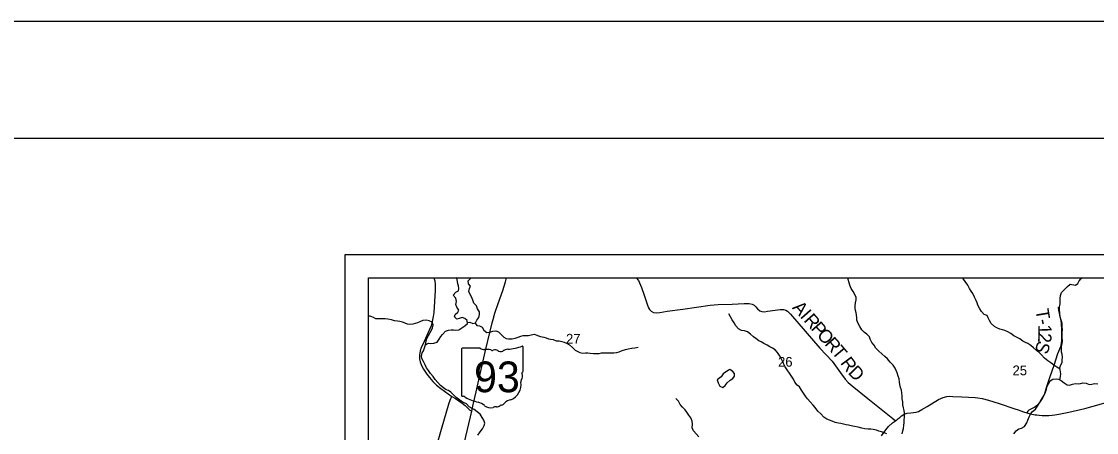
# Model space of a CAD drawing. Extents: x 0 to 34, y 0 to 22.
# Drawn here: x 22.027 to 26.642, y 20.236 to 22 of the extents above; entities that cross this region are included whole.
import ezdxf

# ---------------------------------------------------------------- set-up
doc = ezdxf.new("R2010")
doc.units = 0
for name, color, linetype in [('GM_X_County_Road', 7, 'Continuous'), ('GM_X_County_Road_Text', 7, 'Continuous'), ('GM_X_Major_River', 7, 'Continuous'), ('GM_X_Minor_Lake', 7, 'Continuous'), ('GM_X_Minor_River', 7, 'Continuous'), ('GM_X_Section_Text', 7, 'Continuous'), ('GM_X_State_Location', 7, 'Continuous'), ('GM_X_State_Route', 7, 'Continuous'), ('GM_X_State_Shield', 7, 'Continuous'), ('GM_X_Township_Road', 7, 'Continuous'), ('GM_X_Township_Road_Text', 7, 'Continuous'), ('SH_Border', 7, 'Continuous'), ('SH_Cut_Line', 7, 'Continuous'), ('SH_Data', 7, 'Continuous')]:
    doc.layers.add(name, color=color, linetype=linetype)

msp = doc.modelspace()

# ---------------------------------------------------------------- linework, layer by layer
at = {"layer": 'GM_X_County_Road'}
for points in [[(23.798, 20.9), (23.801, 20.8876), (23.8033, 20.872), (23.8024, 20.8451), (23.7967, 20.7508), (23.7941, 20.7333), (23.7905, 20.7124), (23.7852, 20.6946), (23.779, 20.6783), (23.761, 20.6397), (23.7502, 20.6144), (23.7428, 20.6005), (23.7389, 20.5865), (23.7362, 20.5679), (23.7355, 20.5527), (23.7392, 20.5389), (23.7442, 20.5239), (23.7532, 20.5078), (23.7677, 20.4871), (23.7794, 20.4722), (23.7932, 20.4549), (23.8091, 20.4388), (23.8273, 20.4248), (23.8749, 20.3912), (23.8901, 20.382), (23.9053, 20.3714), (23.9186, 20.3622), (23.9317, 20.3514), (23.9515, 20.3326), (23.96, 20.3273)], [(24.6657, 20.9), (24.6759, 20.8882), (24.689, 20.8583), (24.7005, 20.8261), (24.7148, 20.7822), (24.7189, 20.7716), (24.7228, 20.7647), (24.7309, 20.7566), (24.741, 20.7518), (24.752, 20.7502), (24.7677, 20.7513), (24.7997, 20.7564), (24.8661, 20.7656), (24.9837, 20.7826), (25.0177, 20.7856), (25.0787, 20.7868), (25.1298, 20.79), (25.1514, 20.79), (25.1634, 20.787), (25.1723, 20.7824), (25.1799, 20.7753), (25.1868, 20.7672), (25.1967, 20.7585), (25.2061, 20.7553), (25.2163, 20.7541), (25.2305, 20.7562), (25.2839, 20.764), (25.2988, 20.764), (25.3092, 20.7605), (25.3156, 20.7566), (25.3212, 20.7516), (25.3283, 20.7435), (25.3913, 20.6708), (25.4548, 20.5986), (25.507, 20.542), (25.5427, 20.4923), (25.5639, 20.4654), (25.5767, 20.4514), (25.594, 20.4364), (25.6612, 20.3824), (25.7679, 20.2959), (25.7793, 20.2864)], [(23.7323, 20.033), (23.737, 20.0391), (23.7498, 20.0501), (23.7703, 20.0665), (23.7745, 20.0748), (23.779, 20.0858), (23.7916, 20.1246), (23.8127, 20.1904), (23.833, 20.2612), (23.8405, 20.2846), (23.8637, 20.3631), (23.8706, 20.3822), (23.8749, 20.3912)]]:
    msp.add_lwpolyline(points, dxfattribs=at)
at = {"layer": 'GM_X_Major_River'}
msp.add_lwpolyline([(26.2869, 20.2302), (26.2968, 20.2438), (26.309, 20.2524), (26.3204, 20.2543), (26.3334, 20.2625), (26.3437, 20.2772), (26.348, 20.2886), (26.3534, 20.3029), (26.3588, 20.3143), (26.3676, 20.3256), (26.3802, 20.3369), (26.3893, 20.349), (26.3982, 20.3637), (26.4039, 20.3739), (26.4108, 20.3848), (26.417, 20.3962), (26.4235, 20.409), (26.4274, 20.4219), (26.4309, 20.4332), (26.437, 20.4453), (26.4428, 20.4574), (26.4546, 20.4653), (26.469, 20.4667), (26.4789, 20.4651), (26.4902, 20.4594), (26.503, 20.4498), (26.5163, 20.4413), (26.5265, 20.4397), (26.539, 20.4431), (26.552, 20.4464), (26.5648, 20.4455), (26.5743, 20.4466), (26.5842, 20.4488), (26.5979, 20.4479), (26.6107, 20.4422), (26.6217, 20.444), (26.6343, 20.4465), (26.6475, 20.4449)], dxfattribs=at)
at = {"layer": 'GM_X_Minor_Lake'}
for points in [[(25.0722, 20.5036), (25.0682, 20.5061), (25.0535, 20.4981), (25.0402, 20.4886), (25.0312, 20.4753), (25.0138, 20.4616)], [(25.0138, 20.4616), (25.0177, 20.4495), (25.0256, 20.4351), (25.0378, 20.4287), (25.0476, 20.4382), (25.0563, 20.4488), (25.0702, 20.4606), (25.0804, 20.4678), (25.0887, 20.4785), (25.0876, 20.4891), (25.08, 20.4989), (25.0722, 20.5036)]]:
    msp.add_lwpolyline(points, dxfattribs=at)
at = {"layer": 'GM_X_Minor_River'}
for points in [[(23.7619, 20.6128), (23.774, 20.6197), (23.7838, 20.6178), (23.7978, 20.619), (23.811, 20.6243), (23.8205, 20.6372), (23.8269, 20.6475), (23.8344, 20.6573), (23.848, 20.6706), (23.8601, 20.6748), (23.8722, 20.6768), (23.882, 20.6764), (23.8923, 20.6757), (23.904, 20.6772), (23.9172, 20.6848), (23.9304, 20.6944), (23.9414, 20.7046), (23.941, 20.7168), (23.9311, 20.7251), (23.9193, 20.7303), (23.9057, 20.7258), (23.8959, 20.7227), (23.8856, 20.7325), (23.8883, 20.7428), (23.9007, 20.7523), (23.9045, 20.7618), (23.8954, 20.7739), (23.8919, 20.7849), (23.8941, 20.7981), (23.8918, 20.8125), (23.8808, 20.8258), (23.8914, 20.838), (23.9031, 20.844), (23.9049, 20.8547), (23.9034, 20.8649), (23.9007, 20.8748), (23.8988, 20.8842), (23.8961, 20.8979), (23.8932, 20.9)], [(23.9413, 20.7079), (23.9516, 20.7103), (23.9649, 20.7035), (23.9762, 20.7062), (23.9822, 20.7187), (23.9909, 20.729), (23.9931, 20.7423), (23.9931, 20.754), (23.9855, 20.7665), (23.9798, 20.7798), (23.9695, 20.7908), (23.9649, 20.8036), (23.9584, 20.818), (23.9527, 20.8286), (23.9481, 20.8415), (23.9504, 20.8544), (23.9541, 20.8639), (23.9461, 20.8737), (23.945, 20.8874), (23.9571, 20.9)], [(25.8076, 20.2308), (25.8114, 20.2429), (25.8136, 20.2535), (25.8151, 20.2675), (25.8162, 20.2782), (25.8169, 20.2899), (25.8184, 20.3017), (25.8183, 20.3112), (25.8179, 20.321), (25.8168, 20.3312), (25.8137, 20.3422), (25.8114, 20.3544), (25.8106, 20.368), (25.8087, 20.3813), (25.8079, 20.3923), (25.8071, 20.4067), (25.8051, 20.418), (25.8013, 20.4298), (25.7979, 20.4427), (25.7971, 20.4529), (25.7948, 20.4669), (25.7909, 20.4783), (25.7863, 20.4923), (25.7821, 20.5025), (25.7783, 20.5124), (25.7692, 20.5252), (25.757, 20.5377), (25.7456, 20.5517), (25.7331, 20.5627), (25.7206, 20.574), (25.7073, 20.5846), (25.6948, 20.5979), (25.6875, 20.6103), (25.678, 20.6221), (25.6708, 20.6372), (25.6685, 20.6471), (25.656, 20.6577), (25.6465, 20.6656), (25.6343, 20.6769), (25.6256, 20.6909), (25.6187, 20.7034), (25.6138, 20.7182), (25.6133, 20.7285), (25.6118, 20.7406), (25.6099, 20.7501), (25.6079, 20.7599), (25.6064, 20.7698), (25.6056, 20.78), (25.6075, 20.7925), (25.6108, 20.8058), (25.6104, 20.8153), (25.6051, 20.8278), (25.5971, 20.8414), (25.5887, 20.8546), (25.583, 20.8679), (25.5807, 20.8778), (25.5768, 20.8929), (25.576, 20.9)], [(26.4861, 20.5077), (26.4718, 20.5163), (26.4585, 20.5246), (26.446, 20.5348), (26.4335, 20.5439), (26.4198, 20.5552), (26.4065, 20.5689), (26.3951, 20.5806), (26.3853, 20.5885), (26.3724, 20.6002), (26.3602, 20.6089), (26.3473, 20.6176), (26.3371, 20.6222), (26.3265, 20.6278), (26.3139, 20.638), (26.3018, 20.6437), (26.287, 20.6512), (26.2741, 20.6607), (26.2612, 20.6675), (26.2487, 20.6735), (26.2389, 20.6765), (26.2279, 20.6799), (26.2142, 20.6852), (26.204, 20.6916), (26.1907, 20.7044), (26.1823, 20.7166), (26.1774, 20.7283), (26.1728, 20.7382), (26.1599, 20.7419), (26.1481, 20.7552), (26.1409, 20.7665), (26.1333, 20.7828), (26.1295, 20.793), (26.1249, 20.8055), (26.1188, 20.8169), (26.1108, 20.8328), (26.1043, 20.8426), (26.0971, 20.8544), (26.0895, 20.868), (26.0785, 20.8835), (26.072, 20.8941), (26.0674, 20.9)], [(26.4849, 20.4621), (26.4882, 20.4758), (26.4886, 20.4876), (26.4854, 20.5133), (26.4873, 20.5232), (26.4952, 20.5369), (26.4952, 20.5463), (26.4967, 20.5592), (26.4951, 20.5717), (26.4924, 20.5812), (26.4916, 20.5941), (26.4927, 20.6055), (26.495, 20.6165), (26.4957, 20.6294), (26.4953, 20.643), (26.4948, 20.6555), (26.4948, 20.665), (26.4959, 20.6771), (26.4955, 20.6904), (26.4943, 20.7033), (26.4924, 20.7139), (26.4878, 20.7264), (26.4843, 20.7397), (26.4843, 20.7491), (26.4831, 20.762), (26.4831, 20.7753), (26.4861, 20.7882), (26.4857, 20.8011), (26.486, 20.8113), (26.4879, 20.8246), (26.4927, 20.8375), (26.5052, 20.8497), (26.5173, 20.8622), (26.529, 20.8725), (26.5517, 20.868), (26.5619, 20.8763), (26.5675, 20.887), (26.5762, 20.8968), (26.5805, 20.9)], [(23.7612, 20.611), (23.7641, 20.6299), (23.7675, 20.6397), (23.7746, 20.6526), (23.7821, 20.6659), (23.787, 20.6754), (23.7912, 20.6857), (23.7949, 20.6982), (23.79, 20.7099), (23.7774, 20.7152), (23.7642, 20.7178), (23.7502, 20.717), (23.7404, 20.7128), (23.7275, 20.7075), (23.7177, 20.7041), (23.7071, 20.7018), (23.6938, 20.7002), (23.684, 20.7013), (23.6745, 20.7055), (23.6624, 20.71), (23.6518, 20.7122), (23.6412, 20.7141), (23.6283, 20.7156), (23.615, 20.719), (23.6003, 20.7231), (23.5885, 20.7238), (23.5738, 20.7242), (23.5628, 20.7238), (23.5484, 20.7237), (23.5382, 20.7294), (23.5238, 20.7354), (23.5167, 20.7354)], [(25.7418, 20.2302), (25.7285, 20.2363), (25.7186, 20.2396), (25.7077, 20.2426), (25.6982, 20.2464), (25.6842, 20.249), (25.6736, 20.2498), (25.6626, 20.2505), (25.6478, 20.2516), (25.6349, 20.2546), (25.6194, 20.2587), (25.6031, 20.2613), (25.5887, 20.2643), (25.5774, 20.267), (25.5679, 20.2692), (25.5561, 20.2726), (25.5448, 20.2741), (25.5345, 20.2763), (25.5205, 20.2797), (25.5076, 20.2842), (25.4967, 20.2888), (25.4845, 20.2929), (25.4716, 20.302), (25.4587, 20.3156), (25.4466, 20.3284), (25.434, 20.3432), (25.4264, 20.353), (25.4127, 20.3678), (25.4021, 20.381), (25.3934, 20.3928), (25.3812, 20.4087), (25.3755, 20.4185), (25.3671, 20.4321), (25.3572, 20.4397), (25.347, 20.4526), (25.3413, 20.4651), (25.3336, 20.4779), (25.3238, 20.4908), (25.3146, 20.5048), (25.3055, 20.518), (25.299, 20.5321), (25.2941, 20.5427), (25.288, 20.5536), (25.2819, 20.5669), (25.2735, 20.579), (25.2632, 20.5915), (25.2519, 20.5987), (25.2405, 20.6032), (25.2284, 20.6115), (25.2147, 20.6187), (25.2022, 20.6258), (25.1927, 20.63), (25.1798, 20.6391), (25.1692, 20.6466), (25.157, 20.6587), (25.1434, 20.6678), (25.1305, 20.6719), (25.118, 20.6742), (25.1051, 20.6806), (25.0945, 20.6942), (25.0865, 20.7063), (25.0785, 20.7192), (25.0705, 20.7324), (25.0636, 20.7457)], [(23.9752, 20.706), (23.9815, 20.6956), (23.9933, 20.6941), (24.0054, 20.6881), (24.0126, 20.6752), (24.0255, 20.665), (24.0377, 20.6669), (24.0513, 20.6708), (24.0634, 20.6731), (24.0755, 20.6689), (24.0865, 20.6568), (24.0983, 20.6447), (24.1085, 20.6402), (24.1184, 20.638), (24.1335, 20.6387), (24.146, 20.6407), (24.1596, 20.6456), (24.171, 20.6502), (24.1812, 20.6521), (24.191, 20.6518), (24.2031, 20.6529), (24.2152, 20.6556), (24.2292, 20.6579), (24.2429, 20.6523), (24.2558, 20.6478), (24.2694, 20.6459), (24.2789, 20.6421), (24.2891, 20.638), (24.2986, 20.6361), (24.3096, 20.6346), (24.3232, 20.6297), (24.3357, 20.629), (24.3474, 20.6271), (24.3569, 20.6241), (24.3664, 20.6196), (24.3804, 20.6121), (24.3922, 20.6003), (24.4043, 20.5894), (24.415, 20.5833), (24.4248, 20.5796), (24.4365, 20.5773), (24.4483, 20.5785), (24.4581, 20.5781), (24.4691, 20.5766), (24.4831, 20.5759), (24.493, 20.5752), (24.5073, 20.5745), (24.5172, 20.5775), (24.5414, 20.5783), (24.5558, 20.578), (24.5702, 20.5784), (24.5823, 20.5796), (24.5932, 20.583), (24.6057, 20.5884), (24.6209, 20.5929), (24.6314, 20.5952), (24.647, 20.5979), (24.6606, 20.5999), (24.6753, 20.6026)], [(23.9861, 20.2251), (23.9963, 20.2392), (24.0061, 20.2521), (24.014, 20.2662), (24.0166, 20.276), (24.0116, 20.2885), (24.0048, 20.301), (23.9956, 20.3143), (23.9835, 20.3245), (23.971, 20.335), (23.9615, 20.3396), (23.9494, 20.3467), (23.938, 20.3596), (23.9281, 20.363), (23.9152, 20.3709), (23.9034, 20.3792), (23.8936, 20.3868), (23.8822, 20.3978), (23.8697, 20.4095), (23.8602, 20.4159), (23.8507, 20.42), (23.8382, 20.4272), (23.8264, 20.4382), (23.8146, 20.451), (23.8032, 20.4635), (23.7941, 20.476), (23.7831, 20.4889), (23.7743, 20.5018), (23.7664, 20.5139), (23.7606, 20.5267), (23.753, 20.5407), (23.7458, 20.5536), (23.7442, 20.5639), (23.7476, 20.5775), (23.7533, 20.587), (23.757, 20.5995), (23.7619, 20.6128)], [(24.9347, 20.218), (24.9119, 20.243), (24.9062, 20.2566), (24.9073, 20.2714), (24.9058, 20.285), (24.9, 20.2987), (24.892, 20.3112), (24.8837, 20.3237), (24.8764, 20.3335), (24.8651, 20.3448), (24.8552, 20.3569), (24.8472, 20.3706), (24.8362, 20.3819)]]:
    msp.add_lwpolyline(points, dxfattribs=at)
at = {"layer": 'GM_X_State_Route'}
for points in [[(24.0549, 20.7336), (24.061, 20.7524), (24.0736, 20.7894), (24.0937, 20.8453), (24.1049, 20.8824), (24.1086, 20.9)], [(23.9665, 20.3566), (23.9676, 20.3615), (23.9791, 20.4108), (23.9911, 20.4621), (24.0127, 20.5562), (24.0198, 20.5874), (24.0476, 20.7071), (24.0543, 20.7317), (24.0549, 20.7336)], [(23.8012, 19.4381), (23.8098, 19.4995), (23.8164, 19.5483), (23.8228, 19.5962), (23.8308, 19.6618), (23.8317, 19.6681), (23.8378, 19.712), (23.8466, 19.7798), (23.8599, 19.8692), (23.875, 19.9586), (23.9292, 20.1943), (23.96, 20.3273), (23.9665, 20.3566)], [(25.7793, 20.2864), (25.7898, 20.2947), (25.7977, 20.3009), (25.8049, 20.3071), (25.8118, 20.3117), (25.8213, 20.3163), (25.8302, 20.3193), (25.845, 20.3212), (25.856, 20.3221), (25.868, 20.3228), (25.8776, 20.3258), (25.893, 20.335), (25.9151, 20.3478), (25.9637, 20.3778), (25.9736, 20.3826), (25.9837, 20.3867), (25.9991, 20.3911), (26.0104, 20.3918), (26.0262, 20.3911), (26.0637, 20.3897), (26.1208, 20.387), (26.1332, 20.3856), (26.1509, 20.3819), (26.1783, 20.3743), (26.2238, 20.3607), (26.2919, 20.3377), (26.3058, 20.333)], [(26.4629, 20.312), (26.4806, 20.3147), (26.5236, 20.323), (26.5926, 20.3391), (26.6637, 20.3594), (26.6835, 20.3651), (26.6957, 20.3672), (26.7046, 20.3676), (26.7099, 20.3676), (26.7191, 20.3674), (26.741, 20.3637), (26.7513, 20.3623), (26.761, 20.361), (26.7679, 20.3614), (26.7776, 20.3623), (26.7902, 20.3637), (26.8171, 20.3686), (26.8445, 20.3725), (26.9058, 20.3793), (26.9246, 20.3812), (26.9361, 20.3835), (26.9486, 20.3879)], [(26.3058, 20.333), (26.329, 20.3251), (26.3435, 20.3212), (26.3577, 20.3161), (26.3796, 20.3124), (26.3865, 20.3113), (26.3966, 20.3099), (26.4095, 20.309), (26.4226, 20.3085), (26.4371, 20.309), (26.452, 20.3103), (26.4629, 20.312)], [(25.7189, 20.2216), (25.7373, 20.2477), (25.7496, 20.2623), (25.767, 20.2783), (25.7793, 20.2864)]]:
    msp.add_lwpolyline(points, dxfattribs=at)
at = {"layer": 'GM_X_State_Shield'}
for p, q in [((23.9166, 20.595), (23.9166, 20.3949)), ((23.9964, 20.5984), (23.9192, 20.5984)), ((24.1802, 20.4987), (24.1802, 20.6034)), ((24.1802, 20.4987), (24.1802, 20.4987))]:
    msp.add_line(p, q, dxfattribs=at)
for centre, radius, start, end in [((23.9196, 20.5954), 0.00305, 98.1301, 188.1301), ((24.0148, 20.6217), 0.0296, 231.6195, 271.1119), ((24.0246, 20.4861), 0.1064, 80.4867, 94.9883), ((24.0487, 20.5965), 0.00855, 219.7921, 297.1024), ((24.0613, 20.5733), 0.0178, 54.4667, 119.1411), ((24.0842, 20.605), 0.0214, 233.8562, 294.8282), ((24.122, 20.5373), 0.0563, 97.3462, 120.7689), ((24.0863, 20.8713), 0.2796, 275.8445, 288.9065), ((24.1773, 20.6038), 0.00294, 351.8621, 97.738), ((24.1796, 20.491), 0.00454, 107.944, 210.337), ((24.1771, 20.4983), 0.00314, 289.6038, 7.7341), ((24.102, 20.4416), 0.0699, 292.3089, 8.9858), ((24.1908, 20.4549), 0.0198, 136.8065, 186.9296), ((24.1507, 20.4778), 0.0273, 340.033, 23.6496), ((23.9196, 20.3944), 0.00308, 171.9584, 258.3066), ((23.9201, 20.4149), 0.0235, 267.339, 280.6039), ((23.9249, 20.3833), 0.00848, 29.7484, 93.2717), ((24.032, 20.5631), 0.2019, 240.4129, 257.1985), ((23.9718, 20.305), 0.0632, 47.1842, 75.836), ((24.0855, 20.348), 0.00601, 65.7517, 132.6484), ((24.0829, 20.3755), 0.0226, 282.8732, 323.2771), ((24.1315, 20.3387), 0.0383, 94.4031, 142.5768), ((24.0401, 20.3823), 0.0401, 230.7004, 286.2918), ((24.0633, 20.3131), 0.0329, 85.6951, 111.2099), ((24.0662, 20.3673), 0.0214, 268.777, 315.5493)]:
    msp.add_arc(centre, radius, start, end, dxfattribs=at)
at = {"layer": 'GM_X_Township_Road'}
msp.add_lwpolyline([(26.4785, 20.7741), (26.4787, 20.7599), (26.4822, 20.7479), (26.4856, 20.735), (26.4882, 20.7235), (26.4905, 20.706), (26.4918, 20.6736), (26.4928, 20.6494), (26.4928, 20.6313), (26.4912, 20.6179), (26.4872, 20.6041), (26.4754, 20.5733), (26.4585, 20.5243), (26.4417, 20.4748), (26.4279, 20.432), (26.4173, 20.3975), (26.4095, 20.3826), (26.4005, 20.3688), (26.3892, 20.3541), (26.3782, 20.3442), (26.3524, 20.332), (26.3476, 20.3271), (26.3435, 20.3212)], dxfattribs=at)
at = {"layer": 'SH_Border'}
msp.add_lwpolyline([(1.5, 21.5), (33.5, 21.5), (33.5, 0.5), (1.5, 0.5)], close=True, dxfattribs=at)
at = {"layer": 'SH_Cut_Line'}
msp.add_lwpolyline([(0, 0), (34, 0), (34, 22), (0, 22)], close=True, dxfattribs=at)
at = {"layer": 'SH_Data'}
for points in [[(23.4167, 21), (30.4167, 21), (30.4167, 14), (23.4167, 14)], [(23.5167, 20.9), (30.3167, 20.9), (30.3167, 14.1), (23.5167, 14.1)]]:
    msp.add_lwpolyline(points, close=True, dxfattribs=at)

# ---------------------------------------------------------------- texts
at = {"layer": 'GM_X_County_Road_Text'}
for s, rotation, p in [('A', 311.5851, (25.3338, 20.7705)), ('I', 311.5813, (25.367, 20.7331)), ('R', 311.5832, (25.3825, 20.7157)), ('P', 311.5858, (25.4135, 20.6807)), ('O', 311.5824, (25.4389, 20.6521)), ('R', 311.4734, (25.4721, 20.6147)), ('T', 309.9631, (25.5027, 20.58)), ('R', 306.5186, (25.5402, 20.5343)), ('D', 313.6134, (25.5729, 20.4909))]:
    msp.add_text(s, height=0.0568, rotation=rotation, dxfattribs=at).set_placement(p)
at = {"layer": 'GM_X_Section_Text'}
for s, p in [('27', (24.3648, 20.6176)), ('26', (25.2752, 20.5185)), ('25', (26.2819, 20.4818))]:
    msp.add_text(s, height=0.04186, rotation=0, dxfattribs=at).set_placement(p)
at = {"layer": 'GM_X_State_Location'}
msp.add_text('93', height=0.000189, rotation=0, dxfattribs=at).set_placement((23.9977, 20.4678))
for s in ['s', 'r']:
    msp.add_text(s, height=0.000189, dxfattribs=at).set_placement((24.0454, 20.4816))
at = {"layer": 'GM_X_State_Shield'}
msp.add_text('93', height=0.13184, dxfattribs=at).set_placement((23.9702, 20.409))
at = {"layer": 'GM_X_Township_Road_Text'}
for s, rotation, p in [('T', 279.4539, (26.3801, 20.7626)), ('1', 272.1914, (26.3917, 20.6982)), ('-', 281.3048, (26.3874, 20.7187)), ('2', 267.7722, (26.393, 20.6644)), ('S', 251.0857, (26.3925, 20.6337))]:
    msp.add_text(s, height=0.0568, rotation=rotation, dxfattribs=at).set_placement(p)

doc.saveas('drawing.dxf')
